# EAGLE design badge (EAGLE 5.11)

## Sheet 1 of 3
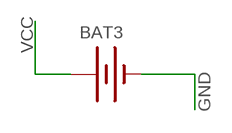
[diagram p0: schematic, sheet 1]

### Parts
BAT3  BATTERYCR123A  [BATTERY_CR123A]

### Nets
GND: BAT3.- ; also sheet 2,3
VCC: BAT3.+ ; also sheet 2,3

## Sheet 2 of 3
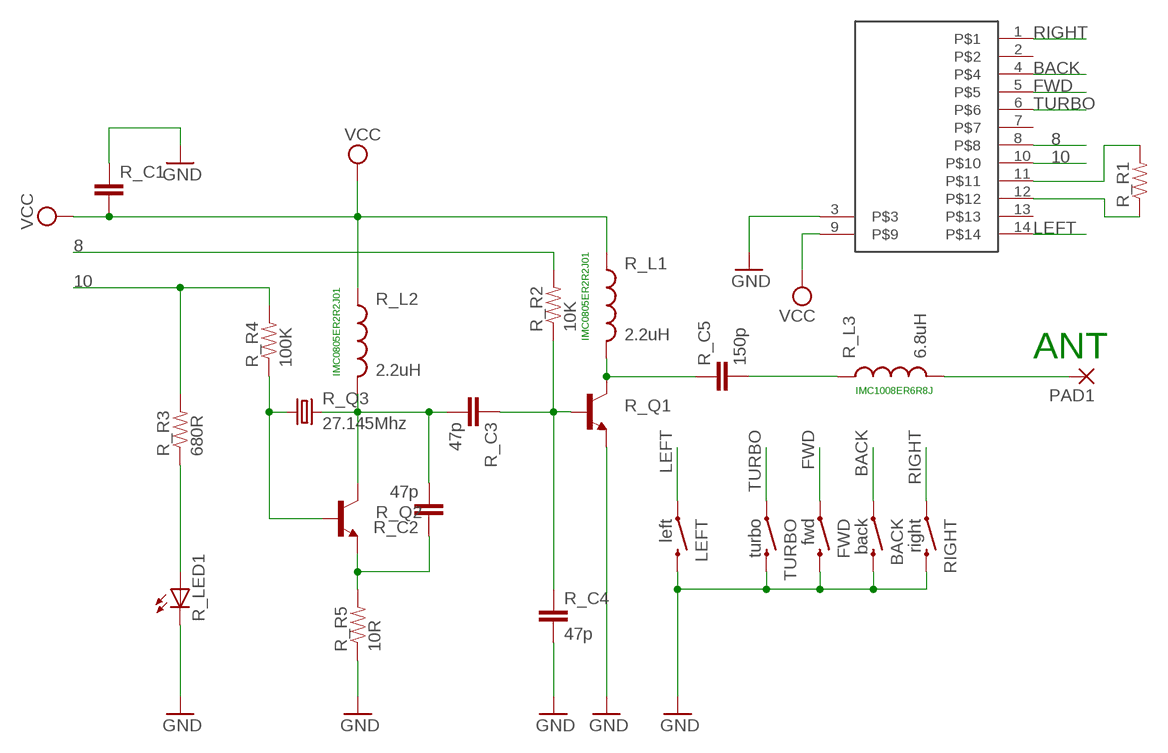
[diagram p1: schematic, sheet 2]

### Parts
BACK  back  SWITCH-MOMENTARY-2-SMD-1101NE  [TACTILE-SWITCH-1101NE]
FWD  fwd  SWITCH-MOMENTARY-2-SMD-1101NE  [TACTILE-SWITCH-1101NE]
LEFT  left  SWITCH-MOMENTARY-2-SMD-1101NE  [TACTILE-SWITCH-1101NE]
PAD1  2,54/1,0  [2,54/1,0]
R_C1  CAP0805  [0805]
R_C2  47p  CAP0805  [0805]
R_C3  47p  CAP0805  [0805]
R_C4  47p  CAP0805  [0805]
R_C5  150p  CAP0805  [0805]
R_L1  2.2uH  INDUCTOR0805  [0805]
R_L2  2.2uH  INDUCTOR0805  [0805]
R_L3  6.8uH  INDUCTOR0805  [0805]
R_LED1  LEDCHIPLED_1206  [CHIPLED_1206]
R_Q1  TRANSISTOR_NPNSOT23-3  [SOT23-3]
R_Q2  TRANSISTOR_NPNSOT23-3  [SOT23-3]
R_Q3  27.145Mhz  CRYSTAL10.5X4.8  [CRYSTAL-SMD-10.5X4.8-2PIN]
R_R1  RESISTORPTH-1/4W  [AXIAL-0.4]
R_R2  10K  RESISTOR  [0805]
R_R3  680R  RESISTOR  [0805]
R_R4  100K  RESISTOR  [0805]
R_R5  10R  RESISTOR  [0805]
R_U1  TX-2B  [DIP14]
RIGHT  right  SWITCH-MOMENTARY-2-SMD-1101NE  [TACTILE-SWITCH-1101NE]
TURBO  turbo  SWITCH-MOMENTARY-2-SMD-1101NE  [TACTILE-SWITCH-1101NE]

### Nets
8: R_R2.2 R_U1.8
10: R_R3.2 R_R4.2 R_U1.10
BACK: BACK.P$1 R_U1.4 ; also sheet 3
FWD: FWD.P$1 R_U1.5 ; also sheet 3
GND: BACK.P$2 FWD.P$2 LEFT.P$2 R_C1.1 R_C4.2 R_LED1.C R_Q1.2(E) R_R5.1 R_U1.3 RIGHT.P$2 TURBO.P$2 ; also sheet 1,3
LEFT: LEFT.P$1 R_U1.14 ; also sheet 3
N$4: R_C5.1 R_L1.2 R_Q1.3(C)
N$10: R_R1.P$2 R_U1.11
N$11: R_R1.P$1 R_U1.12
N$12: R_C3.1 R_C4.1 R_Q1.1(B) R_R2.1
N$13: R_C2.2 R_C3.2 R_L2.2 R_Q2.3(C) R_Q3.P$2
N$14: R_Q2.1(B) R_Q3.P$1 R_R4.1
N$15: R_C2.1 R_Q2.2(E) R_R5.2
N$16: R_LED1.A R_R3.1
N$17: R_C5.2 R_L3.1
N$18: PAD1.1(P) R_L3.2
RIGHT: R_U1.1 RIGHT.P$1 ; also sheet 3
TURBO: R_U1.6 TURBO.P$1 ; also sheet 3
VCC: R_C1.2 R_L1.1 R_L2.1 R_U1.9 ; also sheet 1,3
Unconnected: R_U1.2 R_U1.7 R_U1.13

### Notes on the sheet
- IMC0805ER2R2J01
- ANT
- IMC0805ER2R2J01
- IMC1008ER6R8J

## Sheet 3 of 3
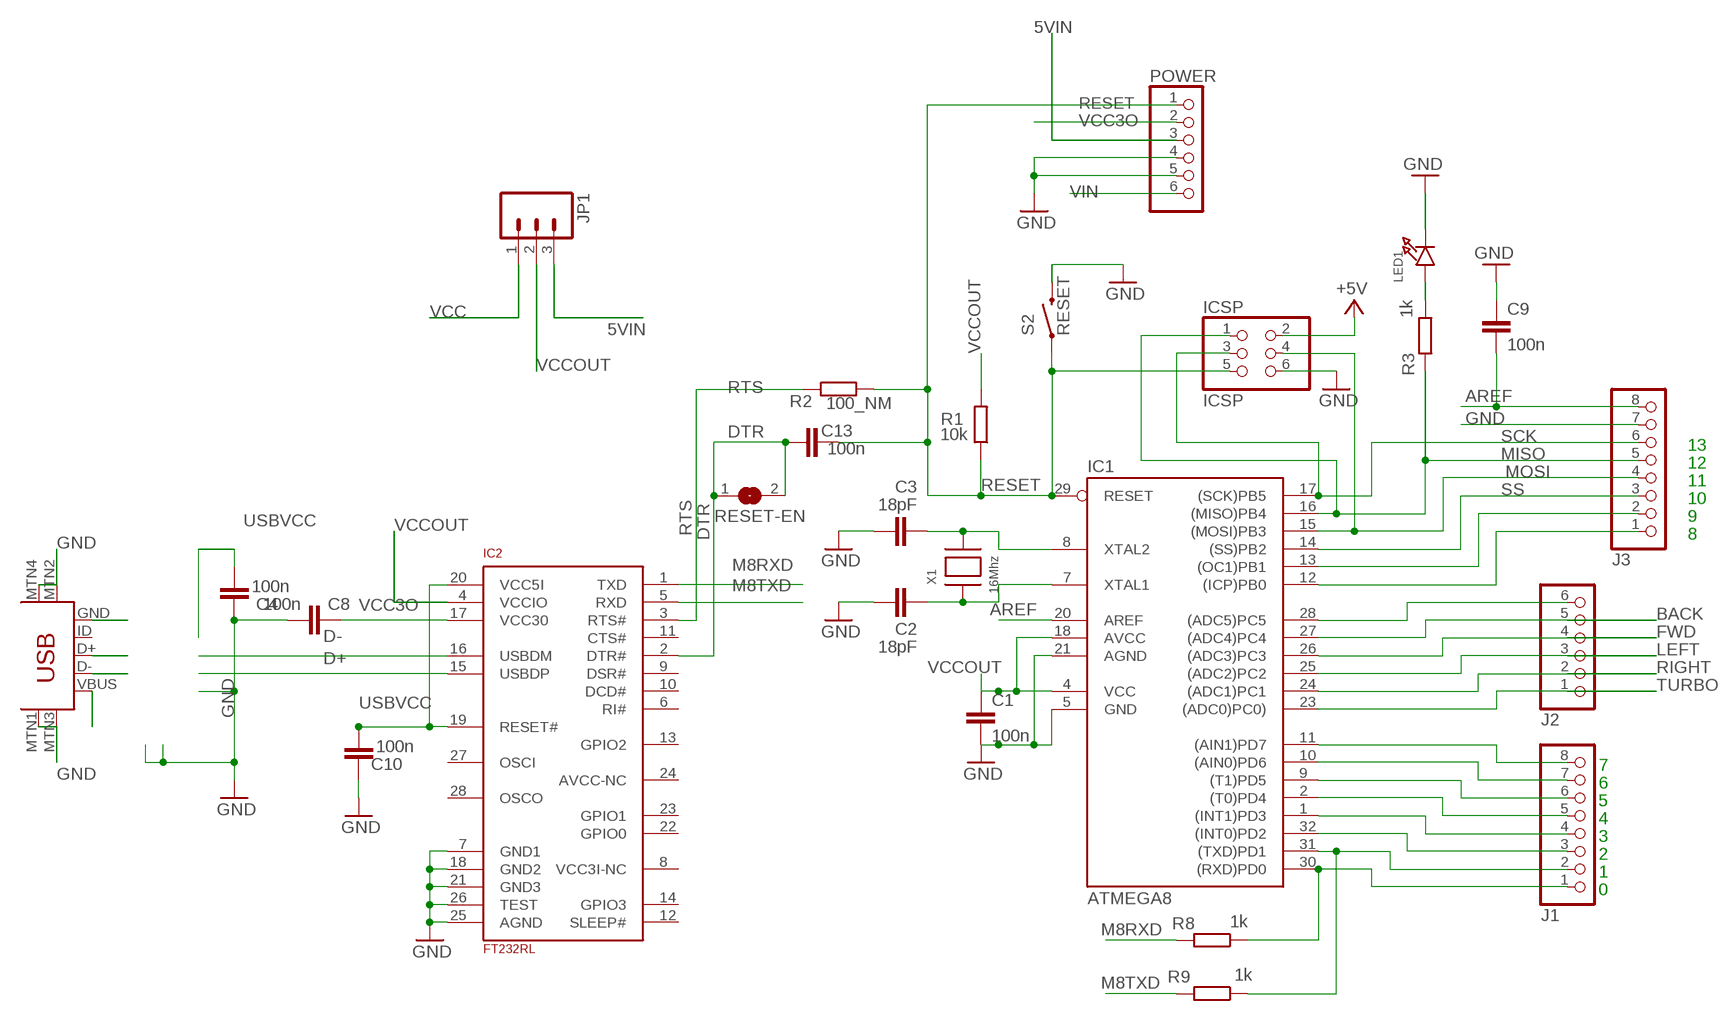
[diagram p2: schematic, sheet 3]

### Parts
C1  100n  C-EU  [C0805RND]
C2  18pF  C-EU  [C0805RND]
C3  18pF  C-EU  [C0805RND]
C4  100n  C-EU  [C0805RND]
C8  100n  C-EU  [C0805RND]
C9  100n  C-EU  [C0805RND]
C10  100n  C-EU  [C0805RND]
C13  100n  C-EU  [C0805RND]
IC1  ATMEGA8  AT90S4433A  [TQFP32-08]
IC2  FT232RL  [SSOP28]
ICSP  ICSP  PINHD-2X3  [2X03]
J1  PINHD-1X8  [1X08]
J2  PINHD-1X6  [1X06]
J3  PINHD-1X8  [1X08]
JP1  M03LOCK_LONGPADS  [1X03_LOCK_LONGPADS]
LED1  LED0805  [CHIPLED_0805]
POWER  PINHD-1X6  [1X06]
R1  10k  R-EU_  [R0805RND]
R2  100_NM  R-EU_  [R0805RND]
R3  1k  R-EU_  [R0805RND]
R8  1k  R-EU_  [R0805RND]
R9  1k  R-EU_  [R0805RND]
RESET-EN  SJ  [SJ]
S2  RESET  SWITCH-MOMENTARY-2-SMD-1101NE  [TACTILE-SWITCH-1101NE]
U$1  USB-MINIB-5PIN  [USB-MINIB]
X1  16Mhz  XTALNX5032  [NX5032]

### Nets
5VIN: JP1.3 POWER.3
AREF [aref]: C9.2 IC1.20(AREF) J3.8
BACK: IC1.27((ADC4)PC4) J2.5 ; also sheet 2
D+: IC2.15(USBDP) U$1.D+
D-: IC2.16(USBDM) U$1.D-
DTR: C13.1 IC2.2(DTR#) RESET-EN.1 RESET-EN.2
FWD: IC1.26((ADC3)PC3) J2.4 ; also sheet 2
GND: C1.2 C2.1 C3.1 C4.2 C8.1 C9.1 C10.2 IC1.5(GND) IC1.21(AGND) IC2.7(GND1) IC2.18(GND2) IC2.21(GND3) IC2.25(AGND) IC2.26(TEST) ICSP.6 J3.7 LED1.C POWER.4 POWER.5 S2.P$2 U$1.GND U$1.MTN1(MTN2) U$1.MTN2(MTN3) U$1.MTN3(MTN1) U$1.MTN4 ; also sheet 1,2
LEFT: IC1.25((ADC2)PC2) J2.3 ; also sheet 2
M8RXD: IC2.1(TXD) R8.2
M8TXD: IC2.5(RXD) R9.2
MISO: IC1.16((MISO)PB4) ICSP.1 J3.5 R3.2
MOSI: IC1.15((MOSI)PB3) ICSP.4 J3.4
N$1: IC1.32((INT0)PD2) J1.3
N$2: IC1.1((INT1)PD3) J1.4
N$3: IC1.2((T0)PD4) J1.5
N$5: IC1.9((T1)PD5) J1.6
N$6: C2.2 IC1.7(XTAL1) X1.P$1
N$7: C3.2 IC1.8(XTAL2) X1.P$2
N$8: IC1.10((AIN0)PD6) J1.7
N$9: IC1.11((AIN1)PD7) J1.8
N$19: LED1.A R3.1
N$24: IC1.28((ADC5)PC5) J2.6
N$25: IC1.12((ICP)PB0) J3.1
N$26: IC1.13((OC1)PB1) J3.2
PD0: IC1.30((RXD)PD0) J1.1 R8.1
PD1: IC1.31((TXD)PD1) J1.2 R9.1
RESET: C13.2 IC1.29(RESET) ICSP.5 POWER.1 R1.1 R2.2 S2.P$1
RIGHT: IC1.24((ADC1)PC1) J2.2 ; also sheet 2
RTS: IC2.3(RTS#) R2.1
SCK: IC1.17((SCK)PB5) ICSP.3 J3.6
SS: IC1.14((SS)PB2) J3.3
TURBO: IC1.23((ADC0)PC0)) J2.1 ; also sheet 2
USBVCC [usbvcc]: C4.1 C10.1 IC2.19(RESET#) IC2.20(VCC5I) U$1.VBUS
VCC: JP1.1 ; also sheet 1,2
VCC3O: C8.2 IC2.17(VCC30) POWER.2
VCCOUT [usbvcc]: C1.1 IC1.4(VCC) IC1.18(AVCC) IC2.4(VCCIO) ICSP.2 JP1.2 R1.2 ; supply symbol labelled +5V
VIN [power]: POWER.6
Unconnected: IC2.6(RI#) IC2.8(VCC3I-NC) IC2.9(DSR#) IC2.10(DCD#) IC2.11(CTS#) IC2.12(SLEEP#) IC2.13(GPIO2) IC2.14(GPIO3) IC2.22(GPIO0) IC2.23(GPIO1) IC2.24(AVCC-NC) IC2.27(OSCI) IC2.28(OSCO) U$1.ID

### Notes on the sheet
- 13
- 12
- 11
- 10
- 9
- 8
- 7
- 6
- 5
- 4
- 3
- 2
- 1
- 0

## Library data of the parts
BACK FWD LEFT RIGHT TURBO = rf_blinky:SWITCH-MOMENTARY-2
BAT3 = tvbgone-adj:BATTERY: Battery Holders
C1-C4 C8-C10 C13 = rcl:C-EU: CAPACITOR, European symbol
IC1 = atmel:AT90S4433: MICROCONTROLLER 4 Kbytes FLASH 128 bytes SRAM 256 bytes EEPROM UART 6-channel 10 bit ADC
IC2 = SmartPrj:FT232RL
ICSP = pinhead:PINHD-2X3: PIN HEADER
J1 J3 = pinhead:PINHD-1X8: PIN HEADER
J2 POWER = pinhead:PINHD-1X6: PIN HEADER
JP1 = SparkFun:M03: Header 3 Standard 3-pin 0.1" header. Use with straight break away headers (SKU : PRT-00116), right angle break away headers (PRT-00553), swiss pins (PRT-00743), machine pins (PRT-00117), and female headers (PRT-00115). Molex polarized connector foot print use with SKU : PRT-08232 with associated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
LED1 = microbuilder:LED: LED
PAD1 = wirepad:2,54/1,0: THROUGH-HOLE PAD
R1-R3 R8 R9 = rcl:R-EU_: RESISTOR, European symbol
R_C1-R_C5 = SparkFun:CAP: Capacitor
R_L1-R_L3 = rf_blinky:INDUCTOR: Inductors
R_LED1 = led:LED: LED
R_Q1 R_Q2 = SparkFun:TRANSISTOR_NPN: Transistor NPN BJT configuration in SOT23 package. MMBT2222 is the common NPN we use. Double check BCE configuration again layout.
R_Q3 = SparkFun:CRYSTAL: Crystals
R_R1 = rf_blinky:RESISTOR: Resistor
R_R2-R_R5 = V3_slice_noshift:RESISTOR: Resistor
R_U1 = badge:TX-2B
RESET-EN = jumper:SJ: SMD solder JUMPER
S2 = SparkFun:SWITCH-MOMENTARY-2
U$1 = SparkFun:USB-MINIB: Mini-USB "B" connector with 5th pin broken out. Created new symbol breaking out 5th "ID" pin in mini/micro USB connector spec. See: http://en.wikipedia.org/wiki/Mini_usb#Cables. Uses same footprint as 4-pin symbol. Also added pins to connect to mounting / shield pads if required (probably not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
X1 = adafruit:XTAL: Low cost SMT crystals, no capacitors included

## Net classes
0 default: width 0.254 mm, drill 0.305 mm, clearance 0.152 mm
1 power: width 0.61 mm, drill 0.508 mm, clearance 0.152 mm
2 gnd: width 0.305 mm, drill 0.508 mm, clearance 0.152 mm
3 usbvcc: width 0.508 mm, drill 0.508 mm, clearance 0.152 mm
4 aref: width 0.406 mm

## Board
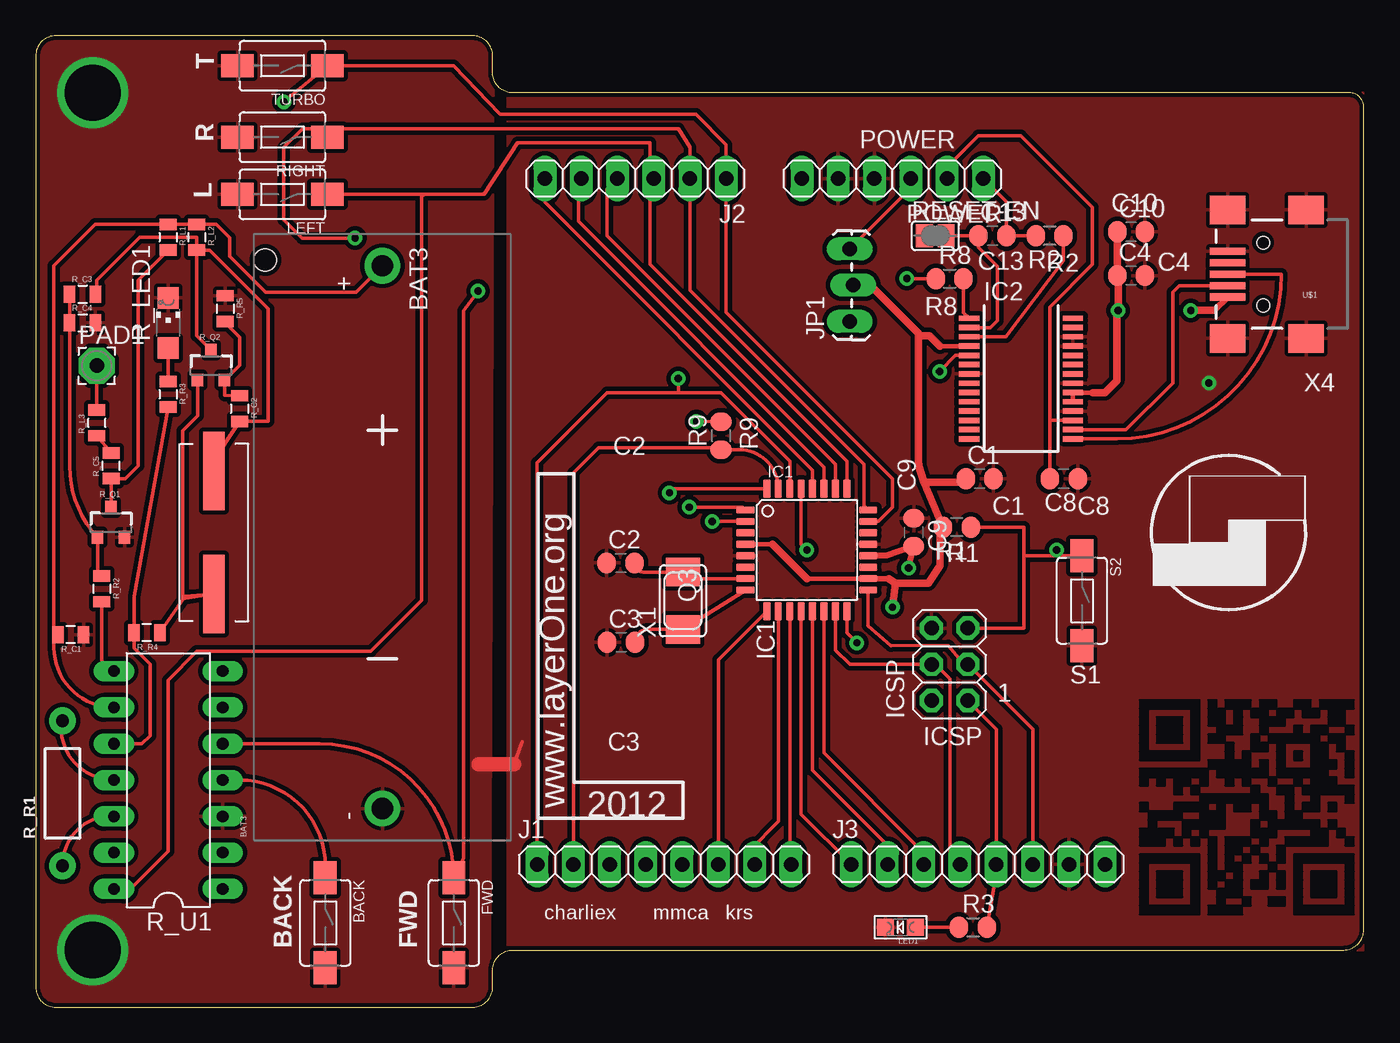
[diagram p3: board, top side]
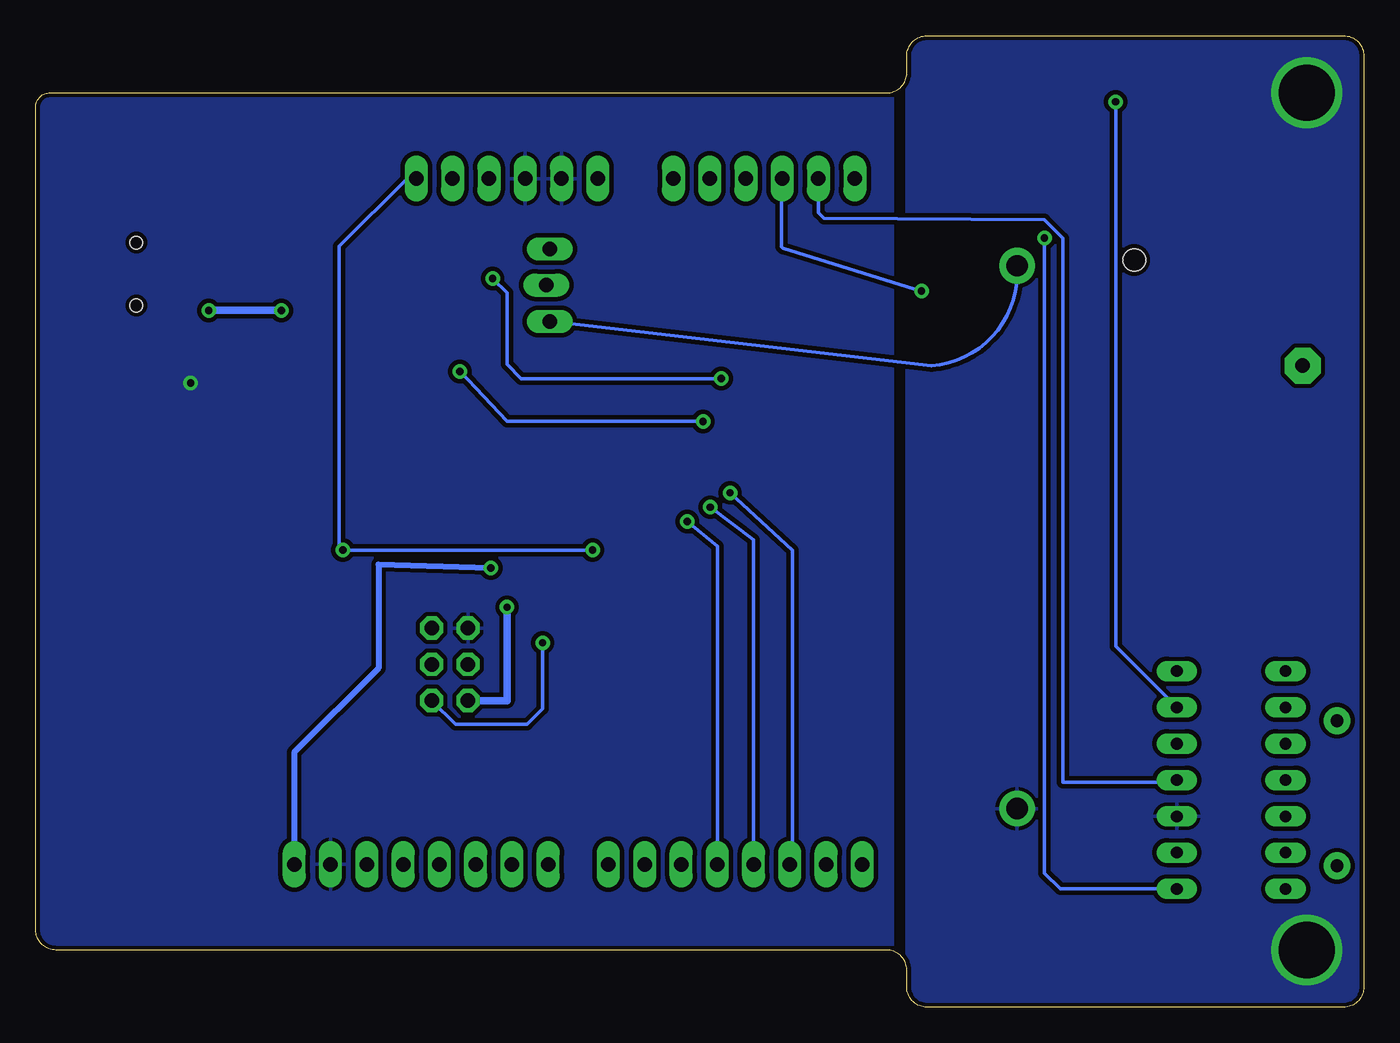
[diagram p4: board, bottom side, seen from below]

Size 93 x 68 mm. Coordinates in mm from the lower left corner, seen from the top.
Outline: 33.41,64 arc-90 32,65.41 32,66.59 arc90 30.59,68 1.41,68 arc90 0,66.59 0,1.41 arc90 1.41,0 30.59,0 arc90 32,1.41 32,2.59 arc-90 33.41,4 91.59,4 arc90 93,5.41 93,63 arc90 92,64 33.41,64
Copper layers (1*16): Top 0.0356mm / dielectric 1.5011mm / Bottom 0.0356mm
Design rules "SparkFun-mod *": minimum track width 8mil, minimum drill 20mil, track to track 12mil, track to pad 12mil, pad to pad 8mil, via to via 8mil, smd to smd 8mil, copper to edge 12mil, drill to drill 8mil, minimum pad ring 12mil, minimum via ring 10mil, stop-mask expansion 4mil, vias tented up to drill 25mil, thermal gap 10mil
tRestrict: area 77.3,6.5 to 77.9,7.1; area 77.3,7.1 to 77.9,7.7; area 77.3,7.7 to 77.9,8.3; area 77.3,8.3 to 77.9,8.9; area 77.3,8.9 to 77.9,9.5; area 77.3,9.5 to 77.9,10.1; area 77.3,10.1 to 77.9,10.7; area 77.3,11.3 to 77.9,11.9; area 77.3,11.9 to 77.9,12.5; area 77.3,13.7 to 77.9,14.3; area 77.3,15.5 to 77.9,16.1; area 77.3,16.1 to 77.9,16.7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
Milling: 16 lines

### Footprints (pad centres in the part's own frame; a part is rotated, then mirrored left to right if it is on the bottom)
TACTILE-SWITCH-1101NE = smd 2.3 x 1.6: P$1 -3.15,0; P$2 3.15,0
BATTERY_CR123A = drill 1.5 pad 2.5 round: + 19,0; - -19,0 | hole 1.575: 19.4,8.2
C0805RND = smd 1.3 x 1.5: 1 -0.977,0; 2 0.977,0
TQFP32-08 = smd 1.27 x 0.508: 1 -4.293,2.8; 2 -4.293,2; 3 -4.293,1.2; 4 -4.293,0.4; 5 -4.293,-0.4; 6 -4.293,-1.2; 7 -4.293,-2; 8 -4.293,-2.8; 17 4.293,-2.8; 18 4.293,-2; 19 4.293,-1.2; 20 4.293,-0.4; 21 4.293,0.4; 22 4.293,1.2; 23 4.293,2; 24 4.293,2.8 | smd 0.508 x 1.27: 9 -2.8,-4.293; 10 -2,-4.293; 11 -1.2,-4.293; 12 -0.4,-4.293; 13 0.4,-4.293; 14 1.2,-4.293; 15 2,-4.293; 16 2.8,-4.293; 25 2.8,4.293; 26 2,4.293; 27 1.2,4.293; 28 0.4,4.293; 29 -0.4,4.293; 30 -1.2,4.293; 31 -2,4.293; 32 -2.8,4.293
SSOP28 = smd 0.381 x 1.499: 1 -4.225,-3.625; 2 -3.575,-3.625; 3 -2.925,-3.625; 4 -2.275,-3.625; 5 -1.625,-3.625; 6 -0.975,-3.625; 7 -0.325,-3.625; 8 0.325,-3.625; 9 0.975,-3.625; 10 1.625,-3.625; 11 2.275,-3.625; 12 2.925,-3.625; 13 3.575,-3.625; 14 4.225,-3.625; 15 4.225,3.625; 16 3.575,3.625; 17 2.925,3.625; 18 2.275,3.625; 19 1.625,3.625; 20 0.975,3.625; 21 0.325,3.625; 22 -0.325,3.625; 23 -0.975,3.625; 24 -1.625,3.625; 25 -2.275,3.625; 26 -2.925,3.625; 27 -3.575,3.625; 28 -4.225,3.625
2X03 = drill 1.016 octagon: 1 -2.54,-1.27; 2 -2.54,1.27; 3 0,-1.27; 4 0,1.27; 5 2.54,-1.27; 6 2.54,1.27
1X08 = drill 1.016 long: 1 -8.89,0; 2 -6.35,0; 3 -3.81,0; 4 -1.27,0; 5 1.27,0; 6 3.81,0; 7 6.35,0; 8 8.89,0
1X06 = drill 1.016 long: 1 -6.35,0; 2 -3.81,0; 3 -1.27,0; 4 1.27,0; 5 3.81,0; 6 6.35,0
1X03_LOCK_LONGPADS = drill 1.016 long: 1 0,0; 2 2.54,-0.254; 3 5.08,0
CHIPLED_0805 = smd 1.2 x 1.2: A 0,-1.05; C 0,1.05
2,54/1,0 = drill 1.016 pad 2.54 octagon: 1 0,0
R0805RND = smd 1.3 x 1.5: 1 -0.977,0; 2 0.977,0
0805 = smd 0.8 x 1.2: 1 -0.9,0; 2 0.9,0
CHIPLED_1206 = smd 1.5 x 1.5: A 0,-1.75; C 0,1.75
SOT23-3 = smd 0.8 x 0.9: 1 -0.95,-1; 2 0.95,-1; 3 0,1.1
CRYSTAL-SMD-10.5X4.8-2PIN = smd 5.5 x 1.5: P$1 -4.3,0; P$2 4.3,0
AXIAL-0.4 = drill 0.9 pad 1.88 round: P$1 -5.08,0; P$2 5.08,0
DIP14 = drill 0.813 long: 1 -7.62,-3.81; 2 -5.08,-3.81; 3 -2.54,-3.81; 4 0,-3.81; 5 2.54,-3.81; 6 5.08,-3.81; 7 7.62,-3.81; 8 7.62,3.81; 9 5.08,3.81; 10 2.54,3.81; 11 0,3.81; 12 -2.54,3.81; 13 -5.08,3.81; 14 -7.62,3.81
SJ = smd 1.168 x 1.6: 1 -0.762,0; 2 0.762,0
USB-MINIB = smd 2.5 x 0.5: D+ 2.5,0; D- 2.5,0.8; GND 2.5,-1.6; ID 2.5,-0.8; VBUS 2.5,1.6 | smd 2.5 x 2: MTN1 -3,4.5; MTN2 2.5,4.5; MTN3 -3,-4.5; MTN4 2.5,-4.5 | hole 0.9: 0,2.2; 0,-2.2
NX5032 = smd 2 x 2.4: P$1 2,0; P$2 -2,0

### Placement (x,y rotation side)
BACK  20.28,5.9 270 top
BAT3  24.28,32.9 90 top
C1  66.1,37 0 top
C2  40.96,31.09 0 top
C3  40.99,25.54 0 top
C4  76.71,51.21 0 top
C8  72,37 180 top
C9  61.48,33.25 270 top
C10  76.71,54.27 0 top
C13  67,54 0 top
FWD  29.28,5.9 270 top
IC1  54,32 0 top
IC2  69,44 270 top
ICSP  64,24 90 top
J1  44,10 0 top
J2  42,58 180 top
J3  66,10 0 top
JP1  57,48 90 top
LED1  60.56,5.59 90 top
LEFT  17.28,56.9 180 top
PAD1  4.28,44.9 0 top
POWER  60,58 180 top
R1  64.5,33.6 180 top
R2  71,54 180 top
R3  65.64,5.59 0 top
R8  64,51 0 top
R9  48,40 90 top
R_C1  2.45,26.08 180 top
R_C2  14.28,41.9 270 top
R_C3  3.28,49.9 0 top
R_C4  3.28,47.9 0 top
R_C5  5.28,37.9 90 top
R_L1  9.28,53.9 270 top
R_L2  11.28,53.9 270 top
R_L3  4.28,40.9 90 top
R_LED1  9.28,47.9 0 top
R_Q1  5.28,33.9 0 top
R_Q2  12.28,44.9 0 top
R_Q3  12.48,33.23 90 top
R_R1  1.87,14.97 90 top
R_R2  4.63,29.28 270 top
R_R3  9.28,42.9 270 top
R_R4  7.79,26.21 180 top
R_R5  13.28,48.9 270 top
R_U1  9.28,15.9 90 top
RESET-EN  63,54 0 top
RIGHT  17.28,60.9 180 top
S2  73.26,28.45 270 top
TURBO  17.28,65.9 180 top
U$1  85.96,51.31 180 top
X1  45.32,28.45 90 top

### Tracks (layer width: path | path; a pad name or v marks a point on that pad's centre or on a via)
5VIN
  Top 0.254: JP1.3 61.27,57.35 POWER.3
8
  Top 0.254: R_U1.8 arc-90 4.63,24.36 R_R2.2
10
  Top 0.254: R_U1.10 7.44,18.44 8,19 8,24 6.89,25.11 R_R4.2 6.91,28.77 R_R3.2
AREF  (via drill 0.51)
  Top 0.406: IC1.20 59.58,31.6 C9.2 v61.13,30.75
  Bottom 0.406: v61.13,30.75 69,31 69,23.73 74.89,17.84 J3.8
BACK
  Top 0.254: IC1.27 55.2,37.8 38,55 38,57.81 J2.5 | BACK.P$1 20.28,9.9 arc90 14.28,15.9 R_U1.4
  Bottom 0.254: 38.13,57.94 J2.5 38.19,55.61 37.79,55.21 22.36,55.11 21.09,53.84 21.09,15.74 13.25,15.74 arc-90 R_U1.4
D+
  Top 0.254: U$1.D+ 87.23,51.31 arc-90 75.69,39.77 IC2.15
D-
  Top 0.254: U$1.D- 80.08,50.51 79.61,50.04 79.61,43.69 76.34,40.42 IC2.16
DTR
  Top 0.254: RESET-EN.1 RESET-EN.2 C13.1 66.02,53.18 67.34,51.86 67.34,48.05 66.86,47.58 IC2.2
FWD  (via drill 0.51)
  Top 0.254: IC1.26 56,38 40,54 40,57.27 J2.4 | v30.97,50.13 29.98,48.76 29.98,10.6 arc-90 29.28,9.9 FWD.P$1 arc90 19.89,18.44 R_U1.5
  Bottom 0.254: 40.73,57 J2.4 40.77,57.96 40.77,53.23 40.67,53.13 v30.97,50.13
GND  (via drill 0.51, 3.94)
  Top 0.254: 34.05,18.57 33.48,17
  Top 1: 33.48,17 31,17
  other vias: 4,64 4,4 82.15,43.69
  pour Top (isolate 0.254): 29.23,-0.84 arc90 31.77,1.7 32.04,68.53 -0.52,68.54 -0.52,1.7 arc90 2.02,-0.84
  pour Top (isolate 0.076): 33,64 33,4 93,4 93,64
  pour Bottom (isolate 0.254): 32,68 32,-1 -1,-1 -1,68
  pour Bottom (isolate 0.254): 33,64 33,4 93,4 93,64
LEFT
  Top 0.254: IC1.25 56.8,38.2 43,52 43,57.73 J2.3 43,58.27 43,60.5 33.73,60.5 31.4,56.9 27.28,56.9 | R_U1.14 6.66,8.28 9.28,10.9 9.28,22.9 11.28,24.9 23.44,24.9 27.01,28.47 27.01,56.63 arc-90 27.28,56.9 | 27.28,56.9 LEFT.P$1
M8RXD
  Top 0.254: IC2.1 64.98,48.62 R8.2
M8TXD  (via drill 0.51)
  Top 0.254: IC2.5 64.4,45.62 v63.3,44.5 | v46.27,41 47.56,40.98 R9.2
  Bottom 0.254: v63.3,44.5 60,41 v46.27,41
MISO  (via drill 0.51)
  Top 0.254: ICSP.1 67.27,19.46 J3.5 67.27,9.4 R3.2 | IC1.16 56.8,26.2 v57.5,25.5
  Bottom 0.254: v57.5,25.5 57.5,20.9 58.6,19.8 63.61,19.8 ICSP.1
MOSI
  Top 0.254: IC1.15 56,25 57,24 ICSP.4 63,24 64,23 64,10.73 J3.4
N$1  (via drill 0.51)
  Top 0.254: IC1.32 44.67,36.29 v44.38,36
  Bottom 0.254: v44.38,36 40,32 40,10.19 arc90 J1.3
N$2  (via drill 0.51)
  Top 0.254: v45.76,35 49.51,35 IC1.1
  Bottom 0.254: J1.4 42.73,32.73 v45.76,35
N$3  (via drill 0.51)
  Top 0.254: IC1.2 v47.38,34
  Bottom 0.254: J1.5 45.27,32.27 v47.38,34
N$4
  Top 0.254: R_L1.2 7.18,50.9 7.18,37.9 6.28,37 R_C5.1 R_Q1.3
N$5
  Top 0.254: J1.6 47.81,24.32 IC1.9
N$6
  Top 0.254: IC1.7 45.77,30 arc-90 X1.P$1 42.58,30.45 arc-90 C2.2
N$7
  Top 0.254: IC1.8 X1.P$2 42.88,26.45 arc90 C3.2
N$8
  Top 0.254: IC1.10 52,13 50,11 50,10.35 J1.7
N$9
  Top 0.254: IC1.11 52.8,10.09 J1.8
N$10
  Top 0.254: R_U1.11 arc-90 1.77,19.6 R_R1.P$2
N$11
  Top 0.254: R_R1.P$1 arc-90 5.24,13.36 R_U1.12
N$12
  Top 0.254: R_C3.1 R_C4.1 2.38,37.85 arc43 R_Q1.1 4.33,30.48 R_R2.1
N$13
  Top 0.254: R_Q3.P$2 12.28,38 R_C2.2 16.28,41 16.28,48.9 12.18,53 R_L2.2 | R_Q2.3 11.28,47 R_L2.2 | R_L2.2 11.28,53.9 7.28,53.9 4.28,50.9 4.28,50 R_C3.2
N$14
  Top 0.254: R_R4.1 10.45,28.77 R_Q3.P$1 10.28,28.6 10.28,40.33 11.33,41.38 R_Q2.1
N$15
  Top 0.254: R_C2.1 13.23,42.85 R_Q2.2 14.28,44.95 14.28,46.9 13.28,47.9 R_R5.2
N$16
  Top 0.254: R_LED1.A R_R3.1
N$17
  Top 0.254: R_C5.2 R_L3.1
N$18
  Top 0.254: PAD1.1 R_L3.2
N$19
  Top 0.254: R3.1 LED1.A
N$24
  Top 0.254: IC1.28 54.4,37.6 35.65,56.35 J2.6
N$25
  Top 0.254: IC1.12 53.6,13.51 J3.1
N$26
  Top 0.254: IC1.13 54.4,16.6 59.65,11.35 J3.2
PD0  (via drill 0.51)
  Top 0.254: J1.1 35.11,38.11 40,43 45,43 | 45,43 48,43 52.8,38.2 IC1.30 | R8.1 v61,51 | v45,44 45,43
  Bottom 0.254: v61,51 60,50 60,45 59,44 v45,44
PD1
  Top 0.254: IC1.31 arc90 49.27,39.02 R9.1 | R9.1 47.98,39 | J1.2 37.65,37.41 39.4,39.16 47.86,39.16 R9.1
RESET  (via drill 0.51)
  Top 0.254: ICSP.5 69.2,26.54 69.2,31.6 | POWER.1 67.98,56.37 C13.2 R2.2 | IC1.29 53.6,32.4 v54,32 | 69.2,31.6 S2.P$1 71.49,31.6 v71.49,32 | 69.2,31.6 69.2,33.6 R1.1
  Bottom 0.254: POWER.1 67,58 71.74,53.26 71.74,32 v71.49,32 v54,32
RIGHT  (via drill 0.51)
  Top 0.254: IC1.24 58,35.09 58,38 45.81,50.19 J2.2 45.81,60.19 45,61.5 21.03,61.5 | 21.03,61.5 RIGHT.P$1 | v22.36,53.84 18.66,53.84 17.38,55.12 17.38,60.2 18.68,61.5 21.03,61.5
  Bottom 0.254: v22.36,53.84 22.36,9.39 21.25,8.28 R_U1.1
RTS
  Top 0.254: IC2.3 67.92,46.92 71.98,52.25 R2.1
SCK
  Top 0.2: 63.9,25.3 59.9,25.3
  Top 0.254: J3.6 69.81,19.46 ICSP.3 65,24 63.9,25.3 | 59.9,25.3 58.29,26.71 IC1.17
SS
  Top 0.254: IC1.14 55.2,17.8 62,11 62,10.19 J3.3
TURBO  (via drill 0.51)
  Top 0.254: IC1.23 59,34 60,35 60,37 48.35,48.65 J2.1 48.35,60.38 46.23,62.5 32.5,62.5 29.28,65.9 TURBO.P$1 v17.38,63.38
  Bottom 0.254: R_U1.6 17.38,25.27 v17.38,63.38
USBVCC  (via drill 0.51)
  Top 0.3: 74.03,43.02 IC2.20 IC2.19
  Top 0.457: U$1.VBUS 82.52,48.77
  Top 0.508: 74.03,43.02 74.88,43.02 75.7,43.84 75.7,48.67 v75.8,48.77 75.8,51.14 C4.1 C10.1 | 82.52,48.77 v80.88,48.77
  Bottom 0.508: v80.88,48.77 v75.8,48.77
VCC
  Top 0.254: R_U1.9 arc-90 1.28,25.17 1.28,25.76 R_C1.2 arc90 1.28,26.14 1.28,51.9 4.18,54.8 R_L1.1 9.28,54.9 9.38,54.8 R_L2.1 12.62,54.8 13.57,53.85 13.57,52.58 16.11,50.04 22.42,50.04 BAT3.+
  Bottom 0.254: JP1.1 30.28,44.9 arc-90 BAT3.+
VCC3O
  Top 0.254: 71.02,40.98 arc90 71,41 71,49 74,52 74,56 69,61 66,61 63.81,58.81 POWER.2 | 71.02,40.98 C8.2 | 71.02,40.98 71.12,41.08 IC2.17
VCCOUT  (via drill 0.51)
  Top 0.3: IC2.4 63.32,46.27 | IC1.18 54,30 | 51.6,32.4 IC1.4
  Top 0.4: 59.75,30 IC1.18
  Top 0.508: 61.82,37.98 62.19,36.76 | 62.19,36.76 R1.2 63.3,33.48 63.3,30.9 62.5,29.67 60.2,29.67 | JP1.2 58.46,50.54 61.82,47.18 61.82,47 | 60.2,29.67 v60,28 | 54,30 51.6,32.4 | 61.82,47 61.82,37.98 | 61.82,37.98 61.85,38 | 63.32,46.27 62.6,47 61.82,47 | C1.1 64.88,36.76 62.19,36.76 | 60.2,29.67 59.75,30
  Bottom 0.508: ICSP.2 60,21.46 v60,28

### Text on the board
tPlace: T | R | POWER | C10 | L | C4 | C13 | R2 | + | BAT3 | R8 | X4 | R9 | C2 | C9 | C1 | C8 | R1 | Q3 | IC1 | S1 | 1 | C3 | ICSP | 2012 | www.layerOne.org | - | charliex | mmca | krs | BACK | FWD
